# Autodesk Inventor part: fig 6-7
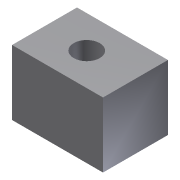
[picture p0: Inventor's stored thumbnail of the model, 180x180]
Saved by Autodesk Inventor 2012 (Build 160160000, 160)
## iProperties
Created: 2009-09
Part Number: fig 6-7
Document SubType Name: Modeling
Designer: Sham
Density: 1 g/cm^3
Material: Default
Author: Sham
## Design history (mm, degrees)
sketch "Sketch1"
  geometry: L1 (-28, 20)-(0, 20); L2 (0, 20)-(0, 0); L3 (0, 0)-(-28, 0); L4 (-28, 0)-(-28, 20)
  constraints: 8 end point, 2 parallel, 1 horizontal, 1 perpendicular
extrude "Extrusion1" new body sketch "Sketch1" distance "d0" = 20; taper "d1" = 0 deg
hole "Hole1" diameter "d4" = 8; stored, may be unused: countersink angle "d8" = 90 deg, drill point angle "d10" = 118 deg; dims "d2" = 10, "d3" = 15, "d5" = 6, "d6" = 4, "d7" = 2, "d9" = 15
body "Solid1"
